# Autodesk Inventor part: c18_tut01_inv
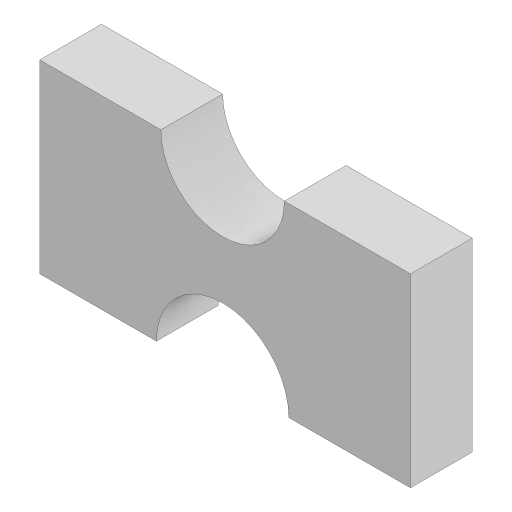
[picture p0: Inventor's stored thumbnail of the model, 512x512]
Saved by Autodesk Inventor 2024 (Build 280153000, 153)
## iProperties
Created: 2019-07
Part Number: c18_tut01_inv
Material: Generic
Document SubType Name: Modeling
Designer: LENOVO-CADCIM
Density: 1 g/cm^3
Appearance: Default
Author: LENOVO-CADCIM
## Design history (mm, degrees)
sketch "Sketch1"
  geometry: L1 (-29.598, 12.811)-(-10, 12.811); L2 (10, 12.811)-(30.402, 12.811); L3 (30.402, 12.811)-(30.402, -17.189); L4 (30.402, -17.189)-(10.723, -17.189); L5 (-10.723, -17.189)-(-29.598, -17.189); L6 (-29.598, -17.189)-(-29.598, 12.811); A1 r 10 centre (0, 12.811) between (-10, 12.811) and (10, 12.811); A2 r 10.723 centre (0, -17.189) between (10.723, -17.189) and (-10.723, -17.189); 1 further point
  constraints: 12 end point, 6 point on line, 4 point on circle, 3 perpendicular, 2 centre point, 1 horizontal
  dimensions: "d0" = 60 distance between parallel lines of L3 L6 (= LEN); "d1" = 30 distance of L5.end L1.start (= WID); "d2" = 10 radius of A1 (= RAD)
extrude "Extrusion1" new body sketch "Sketch1" distance "d3" = 10; taper "d4" = 0 deg
body "Solid1"
other parameters: "LEN" = 60 [user parameter; used in 4 equation terms], "WID" = 30 (= 0.5 x LEN) [user parameter; used in 1 equation term], "RAD" = 10 (= 0.166667 x LEN) [user parameter; used in 1 equation term]
